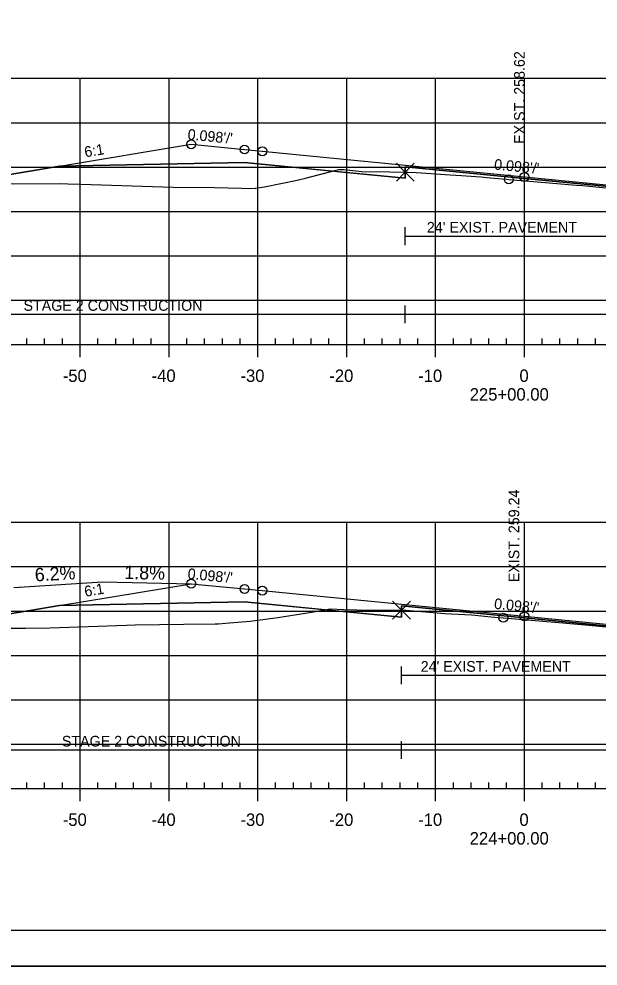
# Model space of a CAD drawing. Extents: x 1365647 to 1367999, y 387113 to 400173.
# Drawn here: x 1365837.2 to 1365902.4, y 391639.5 to 391746.2 of the extents above; entities that cross this region are included whole.
import ezdxf

# ---------------------------------------------------------------- set-up
doc = ezdxf.new("R2010")
doc.units = 0
for name, color, linetype in [('R_Alt Surface', 7, 'Continuous'), ('R_Axis', 7, 'Continuous'), ('R_Axis Annot', 7, 'Continuous'), ('R_Border', 7, 'Continuous'), ('R_Border Notes', 7, 'Continuous'), ('R_Contours', 7, 'Continuous'), ('R_Drive', 7, 'Continuous'), ('R_Exist Surface', 7, 'Continuous'), ('R_Fin Surface', 7, 'Continuous'), ('R_Fin Surface Annot', 7, 'Continuous'), ('R_Grid', 7, 'Continuous'), ('R_No Plot', 7, 'Continuous'), ('R_Water', 7, 'Continuous'), ('R_Xsect Elev', 7, 'Continuous')]:
    doc.layers.add(name, color=color, linetype=linetype)

msp = doc.modelspace()

# ---------------------------------------------------------------- linework, layer by layer
at = {"layer": 'R_Alt Surface'}
for points in [[(1365841.78, 391729.58), (1365862.59, 391729.99), (1365880.68, 391728.23), (1365880.68, 391729.52), (1365894.09, 391728.2), (1365904.35, 391727.2), (1365904.35, 391725.91), (1365925.59, 391723.82), (1365953.01, 391721.13)], [(1365841.78, 391680.09), (1365862.59, 391680.51), (1365880.25, 391678.78), (1365880.25, 391680.07), (1365894.09, 391678.72), (1365903.66, 391677.78), (1365903.66, 391676.49), (1365925.59, 391674.33), (1365953.01, 391671.64)]]:
    msp.add_lwpolyline(points, dxfattribs=at)
at = {"layer": 'R_Axis'}
for p, q in [((1365749.09, 391709.48), (1366039.09, 391709.48)), ((1365838.09, 391709.48), (1365838.09, 391710.18)), ((1365840.09, 391709.48), (1365840.09, 391710.18)), ((1365842.09, 391709.48), (1365842.09, 391710.18)), ((1365844.09, 391708.08), (1365844.09, 391709.48)), ((1365846.09, 391709.48), (1365846.09, 391710.18)), ((1365848.09, 391709.48), (1365848.09, 391710.18)), ((1365850.09, 391709.48), (1365850.09, 391710.18)), ((1365852.09, 391709.48), (1365852.09, 391710.18)), ((1365854.09, 391708.08), (1365854.09, 391709.48)), ((1365856.09, 391709.48), (1365856.09, 391710.18)), ((1365858.09, 391709.48), (1365858.09, 391710.18)), ((1365860.09, 391709.48), (1365860.09, 391710.18)), ((1365862.09, 391709.48), (1365862.09, 391710.18)), ((1365864.09, 391708.08), (1365864.09, 391709.48)), ((1365866.09, 391709.48), (1365866.09, 391710.18)), ((1365868.09, 391709.48), (1365868.09, 391710.18)), ((1365870.09, 391709.48), (1365870.09, 391710.18)), ((1365872.09, 391709.48), (1365872.09, 391710.18)), ((1365874.09, 391708.08), (1365874.09, 391709.48)), ((1365876.09, 391709.48), (1365876.09, 391710.18)), ((1365878.09, 391709.48), (1365878.09, 391710.18)), ((1365880.09, 391709.48), (1365880.09, 391710.18)), ((1365882.09, 391709.48), (1365882.09, 391710.18)), ((1365884.09, 391708.08), (1365884.09, 391709.48)), ((1365886.09, 391709.48), (1365886.09, 391710.18)), ((1365888.09, 391709.48), (1365888.09, 391710.18)), ((1365890.09, 391709.48), (1365890.09, 391710.18)), ((1365892.09, 391709.48), (1365892.09, 391710.18)), ((1365894.09, 391708.08), (1365894.09, 391709.48)), ((1365896.09, 391709.48), (1365896.09, 391710.18)), ((1365898.09, 391709.48), (1365898.09, 391710.18)), ((1365900.09, 391709.48), (1365900.09, 391710.18)), ((1365902.09, 391709.48), (1365902.09, 391710.18)), ((1365838.09, 391659.48), (1365838.09, 391660.18)), ((1365840.09, 391659.48), (1365840.09, 391660.18)), ((1365842.09, 391659.48), (1365842.09, 391660.18)), ((1365846.09, 391659.48), (1365846.09, 391660.18)), ((1365848.09, 391659.48), (1365848.09, 391660.18)), ((1365850.09, 391659.48), (1365850.09, 391660.18)), ((1365852.09, 391659.48), (1365852.09, 391660.18)), ((1365856.09, 391659.48), (1365856.09, 391660.18)), ((1365858.09, 391659.48), (1365858.09, 391660.18)), ((1365860.09, 391659.48), (1365860.09, 391660.18)), ((1365862.09, 391659.48), (1365862.09, 391660.18)), ((1365866.09, 391659.48), (1365866.09, 391660.18)), ((1365868.09, 391659.48), (1365868.09, 391660.18)), ((1365870.09, 391659.48), (1365870.09, 391660.18)), ((1365872.09, 391659.48), (1365872.09, 391660.18)), ((1365876.09, 391659.48), (1365876.09, 391660.18)), ((1365878.09, 391659.48), (1365878.09, 391660.18)), ((1365880.09, 391659.48), (1365880.09, 391660.18)), ((1365882.09, 391659.48), (1365882.09, 391660.18)), ((1365886.09, 391659.48), (1365886.09, 391660.18)), ((1365888.09, 391659.48), (1365888.09, 391660.18)), ((1365890.09, 391659.48), (1365890.09, 391660.18)), ((1365892.09, 391659.48), (1365892.09, 391660.18)), ((1365896.09, 391659.48), (1365896.09, 391660.18)), ((1365898.09, 391659.48), (1365898.09, 391660.18)), ((1365900.09, 391659.48), (1365900.09, 391660.18)), ((1365902.09, 391659.48), (1365902.09, 391660.18)), ((1365749.09, 391659.48), (1366039.09, 391659.48)), ((1365844.09, 391658.08), (1365844.09, 391659.48)), ((1365854.09, 391658.08), (1365854.09, 391659.48)), ((1365864.09, 391658.08), (1365864.09, 391659.48)), ((1365874.09, 391658.08), (1365874.09, 391659.48)), ((1365884.09, 391658.08), (1365884.09, 391659.48)), ((1365894.09, 391658.08), (1365894.09, 391659.48))]:
    msp.add_line(p, q, dxfattribs=at)
at = {"layer": 'R_Border'}
msp.add_line((1366052.27, 391643.48), (1365736.09, 391643.48), dxfattribs=at)
at = {"layer": 'R_Border Notes'}
msp.add_line((1365846.59, 391682.76), (1365856.59, 391682.56), dxfattribs=at)
at = {"layer": 'R_Contours'}
for points in [[(1365832.72, 391727.75), (1365834.15, 391727.7), (1365836.57, 391727.61), (1365841.76, 391727.62), (1365842.71, 391727.61), (1365844.18, 391727.57), (1365854.56, 391727.2), (1365859.19, 391727.18), (1365863.77, 391727.08), (1365863.81, 391727.09), (1365864.83, 391727.26), (1365868.52, 391728.02), (1365869.44, 391728.24), (1365872.47, 391729.03), (1365862.59, 391729.99), (1365841.78, 391729.58), (1365834.59, 391728.38)], [(1365880.68, 391728.91), (1365880.93, 391728.92), (1365881.02, 391728.92), (1365881.92, 391728.86), (1365885.72, 391728.62), (1365887, 391728.53), (1365888.64, 391728.43), (1365889.21, 391728.39), (1365889.84, 391728.32), (1365892.08, 391728.11), (1365892.33, 391728.09), (1365893.24, 391728.01), (1365895.11, 391727.86), (1365897.73, 391727.63), (1365899.95, 391727.46), (1365900.68, 391727.4), (1365903.29, 391727.13), (1365904.35, 391727.03), (1365904.35, 391727.2), (1365894.09, 391728.2), (1365880.68, 391729.52)], [(1365872.47, 391729.03), (1365873.19, 391729.22), (1365873.77, 391729.2), (1365875.8, 391728.99), (1365878.95, 391728.96), (1365880.68, 391728.91), (1365880.68, 391728.23)], [(1365830.4, 391677.5), (1365832.28, 391677.51), (1365835.52, 391677.53), (1365837.92, 391677.55), (1365840.66, 391677.57), (1365849.32, 391677.89), (1365850.29, 391677.93), (1365855.76, 391678), (1365859.3, 391678.04), (1365859.64, 391678.05), (1365860.43, 391678.13), (1365863.23, 391678.35), (1365864.65, 391678.53), (1365866.33, 391678.76), (1365869.69, 391679.29), (1365871.65, 391679.62), (1365862.59, 391680.51), (1365841.78, 391680.09), (1365834.59, 391678.9)], [(1365871.65, 391679.62), (1365872.24, 391679.72), (1365873.76, 391679.64), (1365875.23, 391679.6), (1365880.23, 391679.58), (1365880.25, 391679.58), (1365880.25, 391678.78)], [(1365880.25, 391679.58), (1365880.72, 391679.58), (1365880.75, 391679.58), (1365885.12, 391679.2), (1365885.13, 391679.2), (1365888.12, 391679.04), (1365888.12, 391679.04), (1365888.53, 391679), (1365890.32, 391678.84), (1365890.32, 391678.84), (1365891.71, 391678.72), (1365891.71, 391678.72), (1365891.73, 391678.71), (1365897.51, 391678.22), (1365897.54, 391678.22), (1365900.51, 391677.97), (1365900.57, 391677.97), (1365903.66, 391677.67), (1365903.66, 391677.78), (1365894.09, 391678.72), (1365880.25, 391680.07)]]:
    msp.add_lwpolyline(points, close=True, dxfattribs=at)
at = {"layer": 'R_Drive'}
msp.add_line((1365836.61, 391682.14), (1365846.59, 391682.76), dxfattribs=at)
at = {"layer": 'R_Exist Surface'}
for points in [[(1365836.57, 391727.61), (1365841.76, 391727.62), (1365842.71, 391727.61), (1365844.18, 391727.57), (1365854.56, 391727.2), (1365859.19, 391727.18), (1365863.77, 391727.08), (1365863.81, 391727.09), (1365864.83, 391727.26), (1365868.52, 391728.02), (1365869.44, 391728.24), (1365873.19, 391729.22), (1365873.77, 391729.2), (1365875.8, 391728.99), (1365878.95, 391728.96), (1365880.68, 391728.91), (1365880.93, 391728.92), (1365881.02, 391728.92), (1365881.92, 391728.86), (1365885.72, 391728.62), (1365887, 391728.53), (1365888.64, 391728.43), (1365889.21, 391728.39), (1365889.84, 391728.32), (1365892.08, 391728.11), (1365892.33, 391728.09), (1365893.24, 391728.01), (1365895.11, 391727.86), (1365897.73, 391727.63), (1365899.95, 391727.46), (1365900.68, 391727.4), (1365903.29, 391727.13)], [(1365835.52, 391677.53), (1365837.92, 391677.55), (1365840.66, 391677.57), (1365849.32, 391677.89), (1365850.29, 391677.93), (1365855.76, 391678), (1365859.3, 391678.04), (1365859.64, 391678.05), (1365860.43, 391678.13), (1365863.23, 391678.35), (1365864.65, 391678.53), (1365866.33, 391678.76), (1365869.69, 391679.29), (1365872.24, 391679.72), (1365873.76, 391679.64), (1365875.23, 391679.6), (1365880.23, 391679.58), (1365880.25, 391679.58), (1365880.72, 391679.58), (1365880.75, 391679.58), (1365885.12, 391679.2), (1365885.13, 391679.2), (1365888.12, 391679.04), (1365888.12, 391679.04), (1365888.12, 391679.04), (1365888.53, 391679), (1365890.32, 391678.84), (1365890.32, 391678.84), (1365891.71, 391678.72), (1365891.71, 391678.72), (1365891.73, 391678.71), (1365897.51, 391678.22), (1365897.54, 391678.22), (1365900.51, 391677.97), (1365900.57, 391677.97), (1365903.66, 391677.67)]]:
    msp.add_lwpolyline(points, dxfattribs=at)
at = {"layer": 'R_Fin Surface'}
for points in [[(1365822.13, 391727.9), (1365827.63, 391726.06), (1365834.59, 391728.38), (1365841.78, 391729.58), (1365856.59, 391732.05), (1365862.59, 391731.46), (1365864.59, 391731.26), (1365894.09, 391728.37), (1365923.59, 391725.48), (1365925.59, 391725.28), (1365931.59, 391724.7), (1365953.01, 391721.13), (1365953.59, 391721.03), (1365960.86, 391718.61), (1365983.15, 391726.04)], [(1365856.59, 391732.05), (1365862.59, 391731.46), (1365864.59, 391731.26), (1365894.09, 391728.37), (1365923.59, 391725.48), (1365925.59, 391725.28), (1365931.59, 391724.7)], [(1365825.6, 391677.51), (1365828.03, 391676.71), (1365834.59, 391678.9), (1365841.78, 391680.09), (1365856.59, 391682.56), (1365862.59, 391681.97), (1365864.59, 391681.78), (1365894.09, 391678.89), (1365923.59, 391676), (1365925.59, 391675.8), (1365931.59, 391675.21), (1365953.01, 391671.64), (1365953.59, 391671.55), (1365957.05, 391670.39), (1365972.56, 391675.56)], [(1365856.59, 391682.56), (1365862.59, 391681.97), (1365864.59, 391681.78), (1365894.09, 391678.89), (1365923.59, 391676), (1365925.59, 391675.8), (1365931.59, 391675.21)]]:
    msp.add_lwpolyline(points, dxfattribs=at)
at = {"layer": 'R_Grid'}
for p, q in [((1365749.09, 391739.48), (1366039.09, 391739.48)), ((1365844.09, 391709.48), (1365844.09, 391739.48)), ((1365854.09, 391709.48), (1365854.09, 391739.48)), ((1365864.09, 391709.48), (1365864.09, 391739.48)), ((1365874.09, 391709.48), (1365874.09, 391739.48)), ((1365884.09, 391709.48), (1365884.09, 391739.48)), ((1365894.09, 391709.48), (1365894.09, 391739.48)), ((1365749.09, 391734.48), (1366039.09, 391734.48)), ((1365749.09, 391729.48), (1366039.09, 391729.48)), ((1365749.09, 391724.48), (1366039.09, 391724.48)), ((1365749.09, 391719.48), (1366039.09, 391719.48)), ((1365749.09, 391714.48), (1366039.09, 391714.48)), ((1365749.09, 391709.48), (1366039.09, 391709.48)), ((1365749.09, 391689.48), (1366039.09, 391689.48)), ((1365844.09, 391659.48), (1365844.09, 391689.48)), ((1365854.09, 391659.48), (1365854.09, 391689.48)), ((1365864.09, 391659.48), (1365864.09, 391689.48)), ((1365874.09, 391659.48), (1365874.09, 391689.48)), ((1365884.09, 391659.48), (1365884.09, 391689.48)), ((1365894.09, 391659.48), (1365894.09, 391689.48)), ((1365749.09, 391684.48), (1366039.09, 391684.48)), ((1365749.09, 391679.48), (1366039.09, 391679.48)), ((1365749.09, 391674.48), (1366039.09, 391674.48)), ((1365749.09, 391669.48), (1366039.09, 391669.48)), ((1365749.09, 391664.48), (1366039.09, 391664.48)), ((1365749.09, 391659.48), (1366039.09, 391659.48))]:
    msp.add_line(p, q, dxfattribs=at)
at = {"layer": 'R_No Plot'}
msp.add_line((1365723.69, 391639.5), (1366057.03, 391639.5), dxfattribs=at)
msp.add_lwpolyline([(1365723.69, 391852.83), (1366057.03, 391852.83), (1366057.03, 391639.49), (1365723.69, 391639.49)], close=True, dxfattribs=at)
for points in [[(1365880.68, 391728.91), (1365879.68, 391729.91), (1365880.68, 391728.91), (1365879.68, 391727.91), (1365880.68, 391728.91), (1365881.68, 391727.91), (1365880.68, 391728.91), (1365881.68, 391729.91)], [(1365880.25, 391679.58), (1365879.25, 391680.58), (1365880.25, 391679.58), (1365879.25, 391678.58), (1365880.25, 391679.58), (1365881.25, 391678.58), (1365880.25, 391679.58), (1365881.25, 391680.58)]]:
    msp.add_lwpolyline(points, dxfattribs=at)
for centre in [(1365856.59, 391732.05), (1365856.59, 391732.05), (1365856.59, 391732.05), (1365856.59, 391732.05), (1365856.59, 391732.05), (1365862.59, 391731.46), (1365862.59, 391731.46), (1365862.59, 391731.46), (1365862.59, 391731.46), (1365862.59, 391731.46), (1365864.59, 391731.26), (1365864.59, 391731.26), (1365864.59, 391731.26), (1365864.59, 391731.26), (1365864.59, 391731.26), (1365892.33, 391728.09), (1365894.09, 391728.37), (1365894.09, 391728.37), (1365894.09, 391728.37), (1365894.09, 391728.37), (1365894.09, 391728.37), (1365856.59, 391682.56), (1365856.59, 391682.56), (1365856.59, 391682.56), (1365856.59, 391682.56), (1365856.59, 391682.56), (1365862.59, 391681.97), (1365862.59, 391681.97), (1365862.59, 391681.97), (1365862.59, 391681.97), (1365862.59, 391681.97), (1365864.59, 391681.78), (1365864.59, 391681.78), (1365864.59, 391681.78), (1365864.59, 391681.78), (1365864.59, 391681.78), (1365894.09, 391678.89), (1365894.09, 391678.89), (1365894.09, 391678.89), (1365894.09, 391678.89), (1365894.09, 391678.89), (1365891.71, 391678.72)]:
    msp.add_circle(centre, 0.5, dxfattribs=at)
at = {"layer": 'R_Water'}
for p, q in [((1365880.68, 391720.7), (1365880.68, 391722.7)), ((1365880.68, 391721.7), (1365904.35, 391721.7)), ((1365880.68, 391711.9), (1365880.68, 391713.9)), ((1365822.13, 391712.9), (1365880.68, 391712.9)), ((1365880.68, 391712.9), (1365983.17, 391712.9)), ((1365880.25, 391671.24), (1365880.25, 391673.24)), ((1365880.25, 391672.24), (1365903.66, 391672.24)), ((1365880.25, 391662.83), (1365880.25, 391664.83)), ((1365825.6, 391663.83), (1365880.25, 391663.83)), ((1365880.25, 391663.83), (1365972.25, 391663.83))]:
    msp.add_line(p, q, dxfattribs=at)

# ---------------------------------------------------------------- texts
at = {"layer": 'R_Axis Annot'}
for s, p in [('-50', (1365842.13, 391705.28)), ('-40', (1365852.13, 391705.28)), ('-30', (1365862.13, 391705.28)), ('-20', (1365872.13, 391705.28)), ('-10', (1365882.13, 391705.28)), ('0', (1365893.53, 391705.28)), ('225+00.00', (1365887.93, 391703.18)), ('-50', (1365842.13, 391655.28)), ('-40', (1365852.13, 391655.28)), ('-30', (1365862.13, 391655.28)), ('-20', (1365872.13, 391655.28)), ('-10', (1365882.13, 391655.28)), ('0', (1365893.53, 391655.28)), ('224+00.00', (1365887.93, 391653.18))]:
    msp.add_text(s, height=1.4, dxfattribs=at).set_placement(p)
at = {"layer": 'R_Drive'}
for s, rotation, p in [('6.2%', 3.0737, (1365839.02, 391682.81)), ('1.8%', 358.854, (1365849.05, 391683.09))]:
    msp.add_text(s, height=1.5, rotation=rotation, dxfattribs=at).set_placement(p)
at = {"layer": 'R_Fin Surface Annot'}
for s, rotation, p in [("0.098'/'", 354.4029, (1365856.14, 391732.59)), ('6:1', 9.4623, (1365844.66, 391730.57)), ("0.098'/'", 354.4029, (1365890.64, 391729.21)), ("0.098'/'", 354.4029, (1365856.14, 391683.11)), ('6:1', 9.4623, (1365844.66, 391681.08)), ("0.098'/'", 354.4029, (1365890.64, 391679.73))]:
    msp.add_text(s, height=1.2, rotation=rotation, dxfattribs=at).set_placement(p)
at = {"layer": 'R_Water'}
for s, p in [("24' EXIST. PAVEMENT", (1365883.11, 391722.1)), ('STAGE 2 CONSTRUCTION', (1365837.71, 391713.29)), ("24' EXIST. PAVEMENT", (1365882.42, 391672.64)), ('STAGE 2 CONSTRUCTION', (1365842.03, 391664.22))]:
    msp.add_text(s, height=1.2, dxfattribs=at).set_placement(p)
at = {"layer": 'R_Xsect Elev'}
for s, p in [('EXIST. 258.62', (1365894.13, 391732.09)), ('EXIST. 259.24', (1365893.51, 391682.72))]:
    msp.add_text(s, height=1.2, rotation=90, dxfattribs=at).set_placement(p)

doc.saveas('drawing.dxf')
